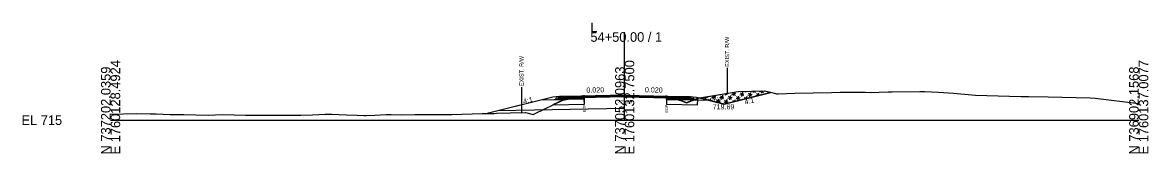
# Model space of a CAD drawing. Extents: x -26 to 4303, y -10 to 9577.
# Drawn here: x 3974.3 to 4302.8, y 4490.3 to 4528.4 of the extents above; entities that cross this region are included whole.
import ezdxf

# ---------------------------------------------------------------- set-up
doc = ezdxf.new("R2010")
doc.units = 0
for name, color, linetype in [('Default', 7, 'Continuous'), ('Exist CMT Pavement', 7, 'Continuous'), ('Old_Level_2', 7, 'Continuous'), ('Pattern 3', 7, 'Continuous'), ('Prop CMT Conc Surface', 7, 'Continuous'), ('Prop CMT Concrete Structures', 7, 'Continuous'), ('Prop CMT Pvmt Course 1', 7, 'Continuous'), ('Prop CMT Pvmt Course 1 CG', 7, 'Continuous'), ('Prop CMT Pvmt Course 2', 7, 'Continuous'), ('Prop CMT Pvmt Course 2 Wedge', 7, 'Continuous'), ('Prop CMT Pvmt Course 3', 7, 'Continuous'), ('Prop CMT Pvmt Surface', 7, 'Continuous'), ('Prop CMT Pvmt Surface Shoulder', 7, 'Continuous'), ('Prop CMT Pvmt Wedge Surface 1', 7, 'Continuous'), ('Prop CMT Pvmt Wedge Surface 2', 7, 'Continuous'), ('Prop CMT Pvmt Wedge Surface 3', 7, 'Continuous'), ('Prop CMT Shld Paved Course 1', 7, 'Continuous'), ('Prop CMT Shld Paved Course 2', 7, 'Continuous'), ('Prop CMT Shld Paved Course 3', 7, 'Continuous'), ('Prop CMT Slope Grass', 7, 'Continuous'), ('Prop CMT Subgrade Earthwork', 7, 'Continuous'), ('Prop Road Sect_ Recs - UC Shallow (Outline)', 7, 'Continuous'), ('Prop Shade Light', 7, 'Continuous'), ('Prop XS DDE Elevations', 7, 'Continuous'), ('Prop XS Ditch Standard Text', 7, 'Continuous'), ('Prop XS Hydro Elevations', 7, 'Continuous'), ('Prop XS SE Text', 7, 'Continuous'), ('Prop XS Side Slope Text', 7, 'Continuous'), ('Prop XS Wedging', 7, 'Continuous'), ('Scratch_Level_2', 7, 'Continuous'), ('Scratch_Level_6', 7, 'Continuous')]:
    doc.layers.add(name, color=color, linetype=linetype)

msp = doc.modelspace()

# ---------------------------------------------------------------- linework, layer by layer
at = {"layer": 'Exist CMT Pavement'}
for points in [[(4150, 4507.23), (4133, 4506.89)], [(4150, 4507.23), (4167, 4506.89)]]:
    msp.add_lwpolyline(points, dxfattribs=at)
at = {"layer": 'Old_Level_2'}
for p, q in [((4150, 4500), (4150, 4525.62)), ((4150, 4500), (4150, 4525.62)), ((4000, 4500), (4150, 4500)), ((4000, 4500), (4150, 4500)), ((4150, 4500), (4300, 4500)), ((4150, 4500), (4300, 4500))]:
    msp.add_line(p, q, dxfattribs=at)
at = {"layer": 'Pattern 3'}
for p, q in [((4178.89, 4507.61), (4179.08, 4507.66)), ((4179.49, 4507.73), (4179.34, 4507.17)), ((4179.53, 4507.74), (4179.94, 4507.33)), ((4181.25, 4507.49), (4182.46, 4507.82)), ((4181.45, 4508.06), (4182.3, 4507.21)), ((4181.99, 4508.15), (4181.69, 4507.05)), ((4182.84, 4508.29), (4182.81, 4508.17)), ((4183.61, 4507.38), (4184.81, 4507.7)), ((4183.77, 4507.98), (4184.65, 4507.1)), ((4184.37, 4508.14), (4184.05, 4506.93)), ((4185.25, 4508.36), (4185.17, 4508.05)), ((4185.61, 4508.37), (4185.77, 4508.21)), ((4185.96, 4507.26), (4187.17, 4507.58)), ((4186.12, 4507.86), (4187.01, 4506.98)), ((4186.73, 4508.02), (4186.41, 4506.81)), ((4187.08, 4508.38), (4187.27, 4508.43)), ((4187.66, 4508.44), (4187.52, 4507.93)), ((4187.78, 4508.44), (4188.13, 4508.1)), ((4188.48, 4507.74), (4189.03, 4507.19)), ((4189.09, 4507.9), (4188.88, 4507.16)), ((4189.44, 4508.26), (4190.45, 4508.53)), ((4190.07, 4508.52), (4189.88, 4507.82)), ((4189.95, 4508.51), (4190.48, 4507.98)), ((4191.8, 4508.14), (4192.12, 4508.23)), ((4192.36, 4508.17), (4192.32, 4508.02)), ((4192.58, 4508.12), (4192.61, 4508.09)), ((4133.29, 4506.1), (4133.65, 4506.19)), ((4133.44, 4506.16), (4133.5, 4506.1)), ((4133.46, 4506.16), (4133.45, 4506.1)), ((4135.37, 4506.47), (4135.69, 4506.15)), ((4135.96, 4506.56), (4135.85, 4506.15)), ((4136.32, 4506.16), (4136.42, 4506.19)), ((4136.8, 4506.64), (4136.77, 4506.54)), ((4137.73, 4506.35), (4137.88, 4506.19)), ((4163.06, 4506.54), (4162.99, 4506.3)), ((4172.71, 4506.38), (4172.68, 4506.27)), ((4173.63, 4506.76), (4173.5, 4506.29)), ((4173.78, 4506.78), (4174.11, 4506.45)), ((4174.46, 4506.1), (4174.83, 4505.73)), ((4175.06, 4506.26), (4174.92, 4505.71)), ((4175.01, 4505.68), (4175.51, 4505.82)), ((4175.42, 4506.61), (4176.63, 4506.94)), ((4175.7, 4507.1), (4176.46, 4506.33)), ((4176.13, 4507.17), (4175.86, 4506.17)), ((4176.66, 4505.37), (4177.86, 4505.7)), ((4176.82, 4505.98), (4177.7, 4505.09)), ((4176.99, 4507.31), (4176.98, 4507.29)), ((4177.42, 4506.14), (4177.16, 4505.15)), ((4177.77, 4506.49), (4178.98, 4506.82)), ((4177.94, 4507.1), (4178.82, 4506.21)), ((4178.54, 4507.26), (4178.22, 4506.05)), ((4178.66, 4504.9), (4178.63, 4504.78)), ((4179.01, 4505.26), (4180.22, 4505.58)), ((4179.17, 4505.86), (4180.06, 4504.98)), ((4179.78, 4506.02), (4179.45, 4504.81)), ((4180.13, 4506.37), (4181.34, 4506.7)), ((4180.29, 4506.98), (4181.18, 4506.09)), ((4180.9, 4507.14), (4180.57, 4505.93)), ((4181.53, 4505.74), (4181.87, 4505.4)), ((4182.13, 4505.9), (4182.01, 4505.44)), ((4182.49, 4506.26), (4183.7, 4506.58)), ((4182.65, 4506.86), (4183.53, 4505.98)), ((4183.25, 4507.02), (4182.93, 4505.81)), ((4185.01, 4506.74), (4185.45, 4506.3)), ((4185.34, 4506.27), (4186.05, 4506.46)), ((4185.61, 4506.9), (4185.45, 4506.3)), ((4188.32, 4507.14), (4189.53, 4507.46))]:
    msp.add_line(p, q, dxfattribs=at)
for points in [[(4192.65, 4508.1), (4179, 4504.69), (4171.88, 4506.47), (4181.97, 4508.14), (4182.48, 4508.29), (4183.15, 4508.3), (4190.83, 4508.54)], [(4138.2, 4506.77), (4138.21, 4506.11), (4132.7, 4506), (4135.3, 4506.5), (4137.55, 4506.71)], [(4164.96, 4506.05), (4162.7, 4506.63), (4162.23, 4506.65), (4162.23, 4506.11)], [(4171.31, 4505.92), (4171.31, 4506.32), (4170.3, 4505.94)]]:
    msp.add_lwpolyline(points, close=True, dxfattribs=at)
at = {"layer": 'Prop CMT Conc Surface'}
for points in [[(4138.21, 4506.74), (4133, 4506.64)], [(4133, 4506.64), (4133, 4506.43)], [(4133, 4506.43), (4138.21, 4506.53)], [(4138.21, 4506.53), (4138.21, 4506.74)], [(4162.23, 4506.52), (4162.23, 4506.73)], [(4162.23, 4506.73), (4167, 4506.64)], [(4167, 4506.43), (4162.23, 4506.52)], [(4167, 4506.64), (4167, 4506.43)]]:
    msp.add_lwpolyline(points, dxfattribs=at)
at = {"layer": 'Prop CMT Concrete Structures'}
for points in [[(4133, 4506.64), (4133, 4506.89)], [(4138.21, 4506.74), (4133, 4506.64)], [(4150, 4507.1), (4138.21, 4506.86)], [(4138.21, 4506.86), (4138.21, 4506.74)], [(4150, 4507.1), (4162.23, 4506.86)], [(4162.23, 4506.86), (4162.23, 4506.73)], [(4162.23, 4506.73), (4167, 4506.64)], [(4167, 4506.64), (4167, 4506.89)]]:
    msp.add_lwpolyline(points, dxfattribs=at)
at = {"layer": 'Prop CMT Pvmt Course 1'}
for points in [[(4138.21, 4506.53), (4133, 4506.43)], [(4133, 4506.43), (4133, 4506.09)], [(4133, 4506.09), (4138.21, 4506.2)], [(4138.21, 4506.2), (4138.21, 4506.53)], [(4162.23, 4506.52), (4167, 4506.43)], [(4162.23, 4506.19), (4162.23, 4506.52)], [(4167, 4506.09), (4162.23, 4506.19)], [(4167, 4506.43), (4167, 4506.09)]]:
    msp.add_lwpolyline(points, dxfattribs=at)
at = {"layer": 'Prop CMT Pvmt Course 2'}
for points in [[(4133, 4506.89), (4131, 4506.85), (4130.74, 4506.59)], [(4130.74, 4506.59), (4133, 4506.64)], [(4133, 4506.64), (4133, 4506.89)], [(4167, 4506.89), (4169, 4506.85), (4169.26, 4506.59)], [(4167, 4506.64), (4167, 4506.89)], [(4169.26, 4506.59), (4167, 4506.64)]]:
    msp.add_lwpolyline(points, dxfattribs=at)
at = {"layer": 'Prop CMT Pvmt Course 2 Wedge'}
for points in [[(4169, 4506.85), (4171, 4506.69), (4179, 4504.69), (4192.65, 4508.1)], [(4131, 4506.85), (4129, 4506.69), (4109.93, 4501.92)]]:
    msp.add_lwpolyline(points, dxfattribs=at)
at = {"layer": 'Prop CMT Pvmt Course 3'}
for points in [[(4133, 4506.64), (4130.74, 4506.59), (4130.53, 4506.38)], [(4130.53, 4506.38), (4133, 4506.43)], [(4133, 4506.43), (4133, 4506.64)], [(4167, 4506.64), (4169.26, 4506.59), (4169.47, 4506.38)], [(4167, 4506.43), (4167, 4506.64)], [(4169.47, 4506.38), (4167, 4506.43)]]:
    msp.add_lwpolyline(points, dxfattribs=at)
at = {"layer": 'Prop CMT Pvmt Surface'}
for points in [[(4150, 4506.98), (4133, 4506.64)], [(4133, 4506.64), (4133, 4506.89)], [(4150, 4506.98), (4167, 4506.64)], [(4167, 4506.64), (4167, 4506.89)]]:
    msp.add_lwpolyline(points, dxfattribs=at)
at = {"layer": 'Prop CMT Pvmt Surface Shoulder'}
for points in [[(4138.21, 4506.77), (4138.41, 4506.77), (4139.16, 4506.79), (4140.54, 4506.82), (4140.84, 4506.82), (4142.07, 4506.83), (4143.34, 4506.86), (4144.5, 4506.87), (4145.84, 4506.89), (4146.93, 4506.89), (4148.35, 4506.89), (4149.17, 4506.89), (4149.57, 4506.89), (4149.72, 4506.89), (4150, 4506.89)], [(4150, 4506.89), (4150.11, 4506.89), (4150.27, 4506.89), (4150.45, 4506.9), (4150.85, 4506.9), (4151.8, 4506.87), (4153.35, 4506.84), (4154.23, 4506.84), (4155.85, 4506.84), (4156.66, 4506.81), (4158.35, 4506.74), (4158.59, 4506.75), (4160.76, 4506.73), (4162.14, 4506.66), (4162.23, 4506.65)]]:
    msp.add_lwpolyline(points, dxfattribs=at)
at = {"layer": 'Prop CMT Pvmt Wedge Surface 1'}
for p, q in [((4133.02, 4505.97), (4125.53, 4505.82)), ((4138.2, 4506.07), (4133.02, 4505.97)), ((4162.23, 4506.06), (4166.98, 4505.97)), ((4166.98, 4505.97), (4174.47, 4505.82))]:
    msp.add_line(p, q, dxfattribs=at)
for points in [[(4138.2, 4506.07), (4138.21, 4506.77)], [(4162.23, 4506.06), (4162.23, 4506.65)]]:
    msp.add_lwpolyline(points, dxfattribs=at)
at = {"layer": 'Prop CMT Pvmt Wedge Surface 2'}
for points in [[(4138.21, 4506.86), (4138.41, 4506.87), (4139.16, 4506.88), (4140.54, 4506.91), (4140.84, 4506.92), (4142.07, 4506.94), (4143.34, 4506.97), (4144.5, 4506.99), (4145.84, 4507.02), (4146.93, 4507.04), (4148.35, 4507.07), (4149.17, 4507.08), (4149.57, 4507.09), (4149.72, 4507.1), (4150, 4507.1)], [(4150, 4506.98), (4149.72, 4506.97), (4149.57, 4506.97), (4149.17, 4506.96), (4148.35, 4506.94), (4146.93, 4506.91), (4145.84, 4506.89), (4145.33, 4506.88), (4144.5, 4506.87), (4143.34, 4506.86), (4142.07, 4506.83), (4140.84, 4506.82), (4140.54, 4506.82), (4139.16, 4506.79), (4138.41, 4506.77), (4138.21, 4506.77)], [(4138.21, 4506.77), (4138.21, 4506.86)], [(4150, 4507.1), (4150, 4506.98)], [(4150, 4507.1), (4150.11, 4507.1), (4150.27, 4507.1), (4150.45, 4507.09), (4150.85, 4507.08), (4151.8, 4507.06), (4153.35, 4507.03), (4154.23, 4507.02), (4155.85, 4506.98), (4156.66, 4506.97), (4158.35, 4506.93), (4158.59, 4506.93), (4160.76, 4506.89), (4162.14, 4506.86), (4162.23, 4506.86)], [(4162.23, 4506.73), (4162.14, 4506.73), (4160.76, 4506.76), (4158.59, 4506.8), (4158.35, 4506.81), (4156.66, 4506.84), (4155.85, 4506.86), (4154.23, 4506.89), (4153.35, 4506.91), (4151.8, 4506.94), (4150.85, 4506.96), (4150.45, 4506.97), (4150.27, 4506.97), (4150.11, 4506.97), (4150, 4506.98)], [(4162.23, 4506.86), (4162.23, 4506.73)]]:
    msp.add_lwpolyline(points, dxfattribs=at)
at = {"layer": 'Prop CMT Pvmt Wedge Surface 3'}
for points in [[(4150, 4506.89), (4149.72, 4506.89), (4149.57, 4506.89), (4149.17, 4506.89), (4148.35, 4506.89), (4146.93, 4506.89), (4145.84, 4506.89), (4145.33, 4506.88)], [(4145.33, 4506.88), (4145.84, 4506.89)], [(4145.84, 4506.89), (4146.93, 4506.91), (4148.35, 4506.94), (4149.17, 4506.96), (4149.57, 4506.97), (4149.72, 4506.97), (4150, 4506.98)], [(4150, 4506.98), (4150, 4506.89)], [(4150, 4506.98), (4150.11, 4506.97), (4150.27, 4506.97), (4150.45, 4506.97), (4150.85, 4506.96), (4151.8, 4506.94), (4153.35, 4506.91), (4154.23, 4506.89), (4155.85, 4506.86), (4156.66, 4506.84), (4158.35, 4506.81), (4158.59, 4506.8), (4160.76, 4506.76), (4162.14, 4506.73), (4162.23, 4506.73)], [(4162.23, 4506.65), (4162.14, 4506.66), (4160.76, 4506.73), (4158.59, 4506.75), (4158.35, 4506.74), (4156.66, 4506.81), (4155.85, 4506.84), (4154.23, 4506.84), (4153.35, 4506.84), (4151.8, 4506.87), (4150.85, 4506.9), (4150.45, 4506.9), (4150.27, 4506.89), (4150.11, 4506.89), (4150, 4506.89)], [(4162.23, 4506.73), (4162.23, 4506.65)]]:
    msp.add_lwpolyline(points, dxfattribs=at)
at = {"layer": 'Prop CMT Shld Paved Course 1'}
for points in [[(4133, 4506.43), (4133, 4506.89)], [(4150, 4506.77), (4133, 4506.43)], [(4150, 4506.77), (4167, 4506.43)], [(4167, 4506.43), (4167, 4506.89)]]:
    msp.add_lwpolyline(points, dxfattribs=at)
at = {"layer": 'Prop CMT Shld Paved Course 2'}
for points in [[(4133, 4506.89), (4131, 4506.85)], [(4167, 4506.89), (4169, 4506.85)]]:
    msp.add_lwpolyline(points, dxfattribs=at)
at = {"layer": 'Prop CMT Shld Paved Course 3'}
for points in [[(4150, 4507.23), (4133, 4506.89)], [(4133, 4506.89), (4133, 4506.64)], [(4133, 4506.64), (4138.21, 4506.74)], [(4138.21, 4506.86), (4150, 4507.1)], [(4138.21, 4506.74), (4138.21, 4506.86)], [(4150, 4506.98), (4150, 4507.23)], [(4150, 4507.23), (4167, 4506.89)], [(4150, 4507.1), (4150, 4506.98), (4150, 4506.98)], [(4162.23, 4506.86), (4150, 4507.1)], [(4162.23, 4506.73), (4162.23, 4506.86)], [(4167, 4506.64), (4162.23, 4506.73)], [(4167, 4506.89), (4167, 4506.64)]]:
    msp.add_lwpolyline(points, dxfattribs=at)
at = {"layer": 'Prop CMT Slope Grass'}
msp.add_lwpolyline([(4000, 4501.72), (4007.43, 4501.9), (4011.6, 4501.83), (4013.32, 4501.82), (4017.43, 4501.63), (4021.39, 4501.61), (4024.88, 4501.57), (4028.45, 4501.47), (4032.71, 4501.64), (4039.36, 4501.48), (4042.76, 4501.47), (4045.55, 4501.43), (4051.57, 4501.44), (4055.53, 4501.44), (4058.96, 4501.54), (4062.64, 4501.79), (4064.53, 4501.78), (4068.82, 4501.59), (4071.91, 4501.49), (4073.85, 4501.38), (4074.57, 4501.36), (4077.14, 4501.5), (4080.41, 4501.64), (4081.84, 4501.62), (4085.01, 4501.57), (4088.74, 4501.62), (4089.57, 4501.65), (4093.91, 4501.61), (4096.16, 4501.62), (4099.56, 4501.61), (4108.44, 4501.9), (4110.69, 4501.92), (4111.89, 4501.95), (4112.62, 4501.99), (4116.58, 4502.12), (4121.05, 4502.23), (4123.26, 4501.63), (4123.85, 4501.9), (4131.95, 4505.86), (4135.3, 4506.5), (4138.2, 4506.77), (4139.16, 4506.79), (4140.84, 4506.82), (4142.12, 4506.84), (4143.34, 4506.86), (4144.5, 4506.87), (4145.84, 4506.89), (4147.27, 4506.89), (4148.35, 4506.89), (4149.17, 4506.89), (4150.11, 4506.89), (4150.45, 4506.9), (4150.85, 4506.9), (4151.8, 4506.87), (4153.35, 4506.84), (4154.23, 4506.84), (4155.85, 4506.84), (4156.66, 4506.81), (4158.59, 4506.75), (4160.76, 4506.73), (4162.14, 4506.66), (4162.7, 4506.63), (4166.38, 4505.69), (4168.04, 4505.09), (4171.53, 4506.41), (4181.97, 4508.14), (4182.48, 4508.29), (4183.15, 4508.3), (4190.83, 4508.54), (4192.54, 4508.13), (4193.97, 4507.77), (4194.29, 4507.66), (4194.83, 4507.7), (4199.7, 4507.83), (4210.36, 4508.05), (4212.88, 4508.13), (4220.14, 4508.13), (4221.62, 4508.1), (4226.91, 4508.21), (4228.05, 4508.2), (4236.13, 4508.31), (4237.45, 4508.32), (4241.57, 4508.15), (4245.91, 4507.86), (4252.34, 4507.31), (4265.61, 4506.92), (4266.75, 4506.91), (4267.34, 4506.88), (4267.88, 4506.86), (4273.54, 4506.75), (4285.79, 4506.46), (4287.3, 4506.39), (4300, 4504.85)], dxfattribs=at)
at = {"layer": 'Prop CMT Subgrade Earthwork'}
for points in [[(4133, 4506.43), (4130.53, 4506.38), (4130.03, 4506.37), (4129.69, 4506.03)], [(4129.69, 4506.03), (4133, 4506.09)], [(4133, 4506.09), (4133, 4506.43)], [(4167, 4506.43), (4169.47, 4506.38), (4169.97, 4506.37), (4170.31, 4506.03)], [(4167, 4506.09), (4167, 4506.43)], [(4170.31, 4506.03), (4167, 4506.09)]]:
    msp.add_lwpolyline(points, dxfattribs=at)
at = {"layer": 'Prop Road Sect_ Recs - UC Shallow (Outline)'}
for points in [[(4138.24, 4504.62), (4138.21, 4506.11), (4132.7, 4506), (4131.95, 4505.86), (4129.02, 4504.43)], [(4162.2, 4504.61), (4171.28, 4504.42), (4171.31, 4505.92), (4170.3, 4505.94), (4168.04, 4505.09), (4166.38, 4505.68), (4165.58, 4505.89), (4164.96, 4506.05), (4162.23, 4506.11)]]:
    msp.add_lwpolyline(points, close=True, dxfattribs=at)
at = {"layer": 'Prop Shade Light'}
for p, q in [((4131.95, 4505.86), (4129.02, 4504.43)), ((4129.02, 4504.43), (4138.24, 4504.62)), ((4132.7, 4506), (4131.95, 4505.86)), ((4138.21, 4506.11), (4132.7, 4506)), ((4138.24, 4504.62), (4138.21, 4506.11)), ((4162.23, 4506.11), (4162.2, 4504.61)), ((4162.2, 4504.61), (4171.28, 4504.42)), ((4164.96, 4506.05), (4162.23, 4506.11)), ((4171.28, 4504.42), (4171.31, 4505.92))]:
    msp.add_line(p, q, dxfattribs=at)
for points in [[(4168.04, 4505.09), (4166.38, 4505.68), (4164.96, 4506.05)], [(4171.31, 4505.92), (4170.3, 4505.94), (4168.04, 4505.09)]]:
    msp.add_lwpolyline(points, dxfattribs=at)
at = {"layer": 'Prop XS DDE Elevations'}
for points in [[(4182.48, 4508.29), (4183.15, 4508.3), (4190.83, 4508.54), (4192.54, 4508.13), (4192.65, 4508.1), (4179, 4504.69), (4174.47, 4505.82), (4171.88, 4506.47), (4181.97, 4508.14)], [(4112.62, 4501.99), (4116.58, 4502.12), (4121.05, 4502.23), (4123.26, 4501.63), (4123.85, 4501.9), (4131.95, 4505.86), (4132.46, 4505.96), (4125.53, 4505.82), (4109.93, 4501.92), (4110.69, 4501.92), (4111.89, 4501.95)], [(4138.2, 4506.07), (4133.02, 4505.97), (4132.46, 4505.96), (4135.3, 4506.5), (4138.21, 4506.77)], [(4138.21, 4506.77), (4138.41, 4506.77), (4139.16, 4506.79)], [(4139.16, 4506.79), (4140.54, 4506.82), (4140.84, 4506.82)], [(4149.57, 4506.89), (4149.64, 4506.89), (4149.17, 4506.89)], [(4150, 4506.89), (4150.11, 4506.89), (4149.64, 4506.89), (4149.72, 4506.89)], [(4150.11, 4506.89), (4150.45, 4506.9), (4150.27, 4506.89)], [(4156.66, 4506.81), (4158.59, 4506.75), (4158.35, 4506.74)], [(4162.23, 4506.65), (4162.7, 4506.63), (4165.14, 4506.01), (4162.23, 4506.06)], [(4166.98, 4505.97), (4170.2, 4505.9), (4168.04, 4505.09), (4166.38, 4505.69), (4165.14, 4506.01)], [(4170.2, 4505.9), (4174.47, 4505.82), (4171.88, 4506.47), (4171.53, 4506.41)]]:
    msp.add_lwpolyline(points, close=True, dxfattribs=at)
at = {"layer": 'Prop XS Ditch Standard Text'}
for p, q in [((4179.9, 4515.2), (4179.9, 4507.8)), ((4119.9, 4509.6), (4119.9, 4502.2)), ((4138.21, 4506.77), (4138.21, 4504.72)), ((4162.23, 4506.65), (4162.23, 4504.6))]:
    msp.add_line(p, q, dxfattribs=at)
at = {"layer": 'Prop XS Wedging'}
for p, q in [((4138.21, 4506.77), (4138.21, 4507.26)), ((4138.21, 4506.86), (4138.21, 4506.77)), ((4150, 4507.1), (4150, 4507.1)), ((4162.23, 4506.86), (4150, 4507.1)), ((4162.23, 4506.65), (4162.23, 4507.15)), ((4162.23, 4506.65), (4162.23, 4506.86))]:
    msp.add_line(p, q, dxfattribs=at)
for points in [[(4150, 4507.1), (4133, 4506.76)], [(4150, 4507.1), (4150, 4507.1), (4138.21, 4506.86)], [(4138.21, 4506.77), (4139.16, 4506.79), (4140.84, 4506.82), (4142.12, 4506.84), (4143.34, 4506.86), (4144.5, 4506.87), (4145.84, 4506.89), (4147.27, 4506.89), (4148.35, 4506.89), (4149.17, 4506.89), (4150.11, 4506.89), (4150.45, 4506.9), (4150.85, 4506.9), (4151.8, 4506.87), (4153.35, 4506.84), (4154.23, 4506.84), (4155.85, 4506.84), (4156.66, 4506.81), (4158.59, 4506.75), (4160.76, 4506.73), (4162.14, 4506.66), (4162.23, 4506.65)], [(4150, 4507.1), (4167, 4506.76)]]:
    msp.add_lwpolyline(points, dxfattribs=at)
at = {"layer": 'Scratch_Level_2'}
msp.add_line((4164.52, 4506.16), (4164.52, 4506.14), dxfattribs=at)
at = {"layer": 'Scratch_Level_6'}
msp.add_lwpolyline([(4150, 4503.43), (4113.03, 4502.69)], dxfattribs=at)

# ---------------------------------------------------------------- texts
at = {"layer": 'Default'}
msp.add_text('-', height=0.0001, dxfattribs=at).set_placement((4000, 4500))
at = {"layer": 'Old_Level_2'}
for s, p in [('L', (4140, 4525.62)), ('L', (4140, 4525.62)), ('54+50.00 / 1', (4140, 4522.82)), ('54+50.00 / 1', (4140, 4522.82)), ('EL 715', (3974, 4498.6)), ('EL 715', (3974, 4498.6))]:
    msp.add_text(s, height=2.8, dxfattribs=at).set_placement(p)
for s, p in [('E 1760128.4924', (4002.8, 4490)), ('E 1760128.4924', (4002.8, 4490)), ('E 1760132.7500', (4152.8, 4490)), ('E 1760132.7500', (4152.8, 4490)), ('N 737202.0359', (4000, 4490)), ('N 737202.0359', (4000, 4490)), ('N 737052.0963', (4150, 4490)), ('N 737052.0963', (4150, 4490)), ('N 736902.1568', (4300, 4490)), ('N 736902.1568', (4300, 4490)), ('E 1760137.0077', (4302.8, 4490)), ('E 1760137.0077', (4302.8, 4490))]:
    msp.add_text(s, height=2.8, rotation=90, dxfattribs=at).set_placement(p)
at = {"layer": 'Prop CMT Pvmt Course 1 CG'}
msp.add_text('721.89', height=1, dxfattribs=at).set_placement((4147.99, 4504.89))
at = {"layer": 'Prop XS Ditch Standard Text'}
for s, height, p in [('EXIST. R/W', 1.181, (4180.49, 4515.5)), ('EXIST. R/W', 1.181, (4120.49, 4509.9)), ('EOP', 0.787, (4138.6, 4502.32)), ('EOP', 0.787, (4162.62, 4502.2))]:
    msp.add_text(s, height=height, rotation=90, dxfattribs=at).set_placement(p)
at = {"layer": 'Prop XS Hydro Elevations'}
msp.add_text('719.69', height=1.5, dxfattribs=at).set_placement((4175.68, 4503.14))
at = {"layer": 'Prop XS SE Text'}
for rotation, p in [(1.1458, (4138.86, 4508)), (358.8542, (4155.9, 4508.11))]:
    msp.add_text('0.020', height=1.5, rotation=rotation, dxfattribs=at).set_placement(p)
at = {"layer": 'Prop XS Side Slope Text'}
for rotation, p in [(14.0362, (4120.54, 4504.71)), (345.9638, (4175.4, 4505.83)), (14.0362, (4185.16, 4504.49))]:
    msp.add_text('4:1', height=1.5, rotation=rotation, dxfattribs=at).set_placement(p)

doc.saveas('drawing.dxf')
